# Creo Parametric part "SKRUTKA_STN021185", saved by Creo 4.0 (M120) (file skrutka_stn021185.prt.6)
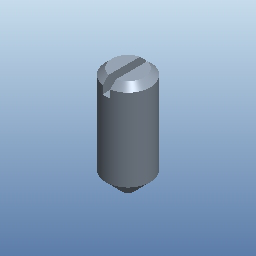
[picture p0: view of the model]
Units: millimeter Kilogram Sec (mmKs); MM, KILOGRAM, SECS
Materials in the file: OCEL

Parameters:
  PTC_MATERIAL_NAME = "OCEL"
  NAZOV = "SKRUTKA_STN021185"
  NORMA = "STN 02 1185"

Other parameters: HMOTNOST, HUSTOTA

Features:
  1. datum plane "DTM2"
  2. cut
  3. datum plane "DTM3"
  4. datum plane "DTM5"

Other named items: THRU

Layers: 1, 2, 3, 4, 5, 6, 7, 8, 9, 10, 11, 12, 13, 14, 15, 16, 17, 18, 19, 20, 21, 22, 23, 24, 25, 26, 27, 28, 29, 30, 31, 32

Family table entries: GENERIC, SKRUTKA_M1_6, SKRUTKA_STN021185, value(d_val), value(i_val), SKRUTKA_M2, SKRUTKA_STN021185, SKRUTKA_M2_5, SKRUTKA_STN021185, SKRUTKA_M3, SKRUTKA_STN021185, SKRUTKA_M3_5, SKRUTKA_STN021185, SKRUTKA_M4, SKRUTKA_STN021185, SKRUTKA_M5, SKRUTKA_STN021185, SKRUTKA_M6, SKRUTKA_STN021185, SKRUTKA_M8, SKRUTKA_STN021185, !/ , SKRUTKA_M10, SKRUTKA_STN021185, !/$, SKRUTKA_M12, SKRUTKA_STN021185, !/(, SKRUTKA_M16, SKRUTKA_STN021185, !/0, # Pro/TABLE, [] S 92;, [] W 10;, [A] W  3;, [B] W 13;, [C] W 10;, [D] W 10;, [E] W 10;, [F] W 10;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

Surfaces: 7 plane, 4 cylinder, 3 cone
